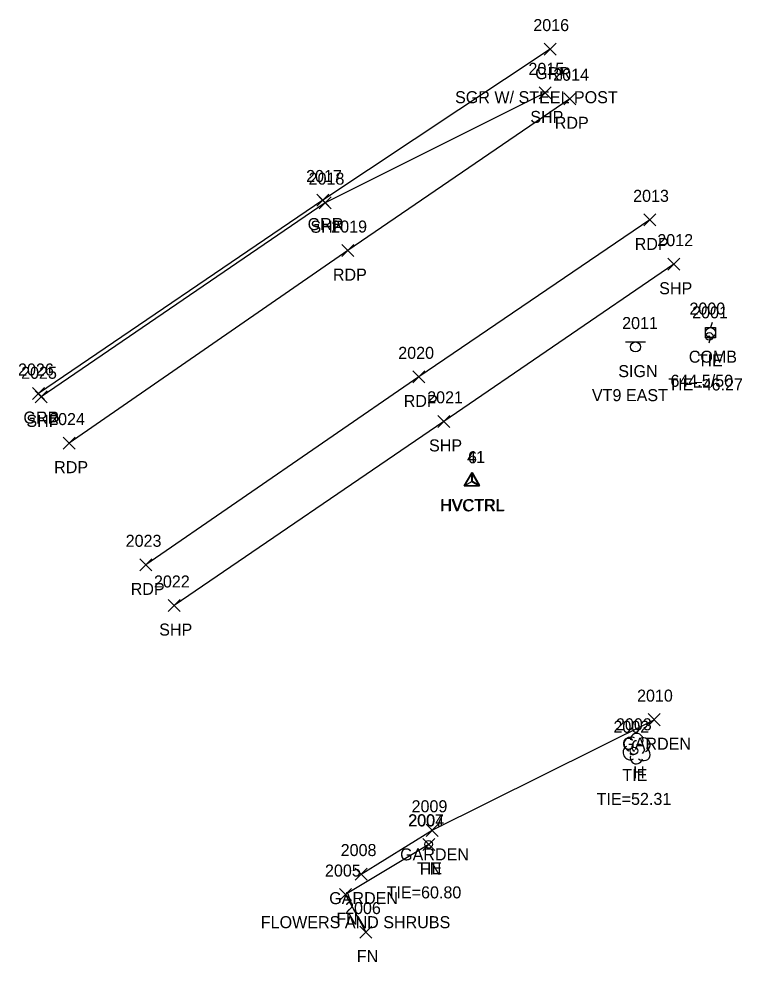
# Model space of a CAD drawing. Extents: x 1502194 to 1507887, y 142265 to 144150.
# Drawn here: x 1507324.3 to 1507444.5, y 143750.3 to 143907.2 of the extents above; entities that cross this region are included whole.
import ezdxf

# ---------------------------------------------------------------- set-up
doc = ezdxf.new("R2010")
doc.units = 0
for name, color, linetype in [('C_A', 7, 'Continuous'), ('C_C', 7, 'Continuous'), ('C_I', 7, 'Continuous'), ('CBP', 7, 'Continuous'), ('CPSM', 7, 'Continuous'), ('L_A', 7, 'Continuous'), ('L_C', 7, 'Continuous'), ('L_I', 7, 'Continuous'), ('L_TIC', 7, 'Continuous'), ('LAPB', 7, 'Continuous'), ('LFNC', 7, 'Continuous'), ('LTD', 7, 'Continuous'), ('P_A', 7, 'Continuous'), ('P_I', 7, 'Continuous'), ('P_TIC', 7, 'Continuous'), ('PET', 7, 'Continuous'), ('PSP', 7, 'Continuous'), ('R_A', 7, 'Continuous'), ('R_C', 7, 'Continuous'), ('R_I', 7, 'Continuous'), ('R_TIC', 7, 'Continuous'), ('RGR', 7, 'Continuous'), ('S_A', 7, 'Continuous'), ('S_C', 7, 'Continuous'), ('S_I', 7, 'Continuous'), ('SSGN', 7, 'Continuous'), ('U_A', 7, 'Continuous'), ('U_C', 7, 'Continuous'), ('U_I', 7, 'Continuous'), ('UP', 7, 'Continuous')]:
    doc.layers.add(name, color=color, linetype=linetype)

msp = doc.modelspace()

# ---------------------------------------------------------------- linework, layer by layer
at = {"layer": 'CBP'}
for centre, radius in [((1507439.08, 143854.37), 0.625), ((1507439.08, 143854.37), 0.0833), ((1507426.55, 143785.42), 0.625), ((1507426.55, 143785.42), 0.0833), ((1507392.41, 143769.87), 0.625), ((1507392.41, 143769.87), 0.0833)]:
    msp.add_circle(centre, radius, dxfattribs=at)
at = {"layer": 'CPSM'}
for p, q in [((1507398.34, 143829.53), (1507399.59, 143831.69)), ((1507398.45, 143829.58), (1507399.7, 143831.74)), ((1507400.84, 143829.53), (1507399.59, 143831.69)), ((1507399.59, 143830.25), (1507399.59, 143831.69)), ((1507400.95, 143829.58), (1507399.7, 143831.74)), ((1507399.7, 143830.3), (1507399.7, 143831.74)), ((1507398.34, 143829.53), (1507399.59, 143830.25)), ((1507398.45, 143829.58), (1507399.7, 143830.3)), ((1507399.59, 143830.25), (1507399.59, 143830.25)), ((1507399.59, 143830.25), (1507400.84, 143829.53)), ((1507399.7, 143830.3), (1507399.7, 143830.3)), ((1507399.7, 143830.3), (1507400.95, 143829.58)), ((1507398.34, 143829.53), (1507400.84, 143829.53)), ((1507398.45, 143829.58), (1507400.95, 143829.58))]:
    msp.add_line(p, q, dxfattribs=at)
at = {"layer": 'L_TIC'}
for points in [[(1507428.93, 143789.6), (1507430.93, 143791.6)], [(1507430.93, 143789.6), (1507428.93, 143791.6)], [(1507392, 143771.19), (1507394, 143773.19)], [(1507394, 143771.19), (1507392, 143773.19)], [(1507391.47, 143768.84), (1507393.47, 143770.84)], [(1507393.47, 143768.84), (1507391.47, 143770.84)], [(1507380.21, 143763.91), (1507382.21, 143765.91)], [(1507382.21, 143763.91), (1507380.21, 143765.91)], [(1507377.59, 143760.5), (1507379.59, 143762.5)], [(1507379.59, 143760.5), (1507377.59, 143762.5)], [(1507380.99, 143754.26), (1507382.99, 143756.26)], [(1507382.99, 143754.26), (1507380.99, 143756.26)]]:
    msp.add_lwpolyline(points, dxfattribs=at)
at = {"layer": 'LAPB'}
msp.add_lwpolyline([(1507381.21, 143764.91), (1507393, 143772.19), (1507429.93, 143790.6)], dxfattribs=at)
at = {"layer": 'LFNC'}
msp.add_lwpolyline([(1507392.47, 143769.84), (1507378.59, 143761.5), (1507381.99, 143755.26)], dxfattribs=at)
at = {"layer": 'LTD'}
msp.add_line((1507426.97, 143785.83), (1507426.97, 143785.83), dxfattribs=at)
msp.add_line((1507426.97, 143785.83), (1507426.97, 143785.83), dxfattribs=at)
msp.add_arc((1507427.02, 143787.26), 1.05, 335.5272, 180.9563, dxfattribs=at)
for centre, major_axis, ratio, start_param, end_param in [((1507426.18, 143786.49), (1.21, -0.51), 0.895232, 1.570796, 4.712389), ((1507428.02, 143786.41), (-1.14, -0.48), 0.949671, 1.570796, 4.712389), ((1507426.77, 143786.28), (-0.208, -0.792), 0.645439, 3.141593, 6.283185), ((1507427.47, 143785.66), (-0.5, 0.667), 0.989748, 3.141593, 6.283185), ((1507425.89, 143785.12), (0.58, -1.04), 0.959034, 3.141593, 6.283185), ((1507426.52, 143785.08), (-0.625, -0.083), 0.423636, 0, 3.141593), ((1507427.97, 143784.99), (-1.09, 0.79), 0.841452, 1.570796, 4.712389), ((1507426.97, 143784.33), (0.26, 1.06), 0.942809, 1.570796, 4.712389)]:
    msp.add_ellipse(centre, major_axis=major_axis, ratio=ratio, start_param=start_param, end_param=end_param, dxfattribs=at)
at = {"layer": 'P_TIC'}
for points in [[(1507410.79, 143893.88), (1507412.79, 143895.88)], [(1507412.79, 143893.88), (1507410.79, 143895.88)], [(1507414.9, 143892.9), (1507416.9, 143894.9)], [(1507416.9, 143892.9), (1507414.9, 143894.9)], [(1507374.23, 143875.61), (1507376.23, 143877.61)], [(1507376.23, 143875.61), (1507374.23, 143877.61)], [(1507428.19, 143872.75), (1507430.19, 143874.75)], [(1507430.19, 143872.75), (1507428.19, 143874.75)], [(1507378, 143867.64), (1507380, 143869.64)], [(1507380, 143867.64), (1507378, 143869.64)], [(1507432.21, 143865.38), (1507434.21, 143867.38)], [(1507434.21, 143865.38), (1507432.21, 143867.38)], [(1507389.78, 143846.63), (1507391.78, 143848.63)], [(1507391.78, 143846.63), (1507389.78, 143848.63)], [(1507326.99, 143843.31), (1507328.99, 143845.31)], [(1507328.99, 143843.31), (1507326.99, 143845.31)], [(1507393.94, 143839.23), (1507395.94, 143841.23)], [(1507395.94, 143839.23), (1507393.94, 143841.23)], [(1507331.65, 143835.61), (1507333.65, 143837.61)], [(1507333.65, 143835.61), (1507331.65, 143837.61)], [(1507344.38, 143815.36), (1507346.38, 143817.36)], [(1507346.38, 143815.36), (1507344.38, 143817.36)], [(1507349.08, 143808.59), (1507351.08, 143810.59)], [(1507351.08, 143808.59), (1507349.08, 143810.59)]]:
    msp.add_lwpolyline(points, dxfattribs=at)
at = {"layer": 'PET'}
for points in [[(1507415.9, 143893.9), (1507379, 143868.64), (1507332.65, 143836.61)], [(1507429.19, 143873.75), (1507390.78, 143847.63), (1507345.38, 143816.36)]]:
    msp.add_lwpolyline(points, dxfattribs=at)
at = {"layer": 'PSP'}
for points in [[(1507411.79, 143894.88), (1507375.23, 143876.61), (1507327.99, 143844.31)], [(1507433.21, 143866.38), (1507394.94, 143840.23), (1507350.08, 143809.59)]]:
    msp.add_lwpolyline(points, dxfattribs=at)
at = {"layer": 'R_TIC'}
for points in [[(1507411.64, 143901.16), (1507413.64, 143903.16)], [(1507413.64, 143901.16), (1507411.64, 143903.16)], [(1507373.81, 143876.05), (1507375.81, 143878.05)], [(1507375.81, 143876.05), (1507373.81, 143878.05)], [(1507326.54, 143843.86), (1507328.54, 143845.86)], [(1507328.54, 143843.86), (1507326.54, 143845.86)]]:
    msp.add_lwpolyline(points, dxfattribs=at)
at = {"layer": 'RGR'}
msp.add_lwpolyline([(1507412.64, 143902.16), (1507374.81, 143877.05), (1507327.54, 143844.86)], dxfattribs=at)
at = {"layer": 'SSGN'}
for p, q in [((1507425.17, 143853.45), (1507428.5, 143853.45)), ((1507426.81, 143852.61), (1507426.81, 143852.61))]:
    msp.add_line(p, q, dxfattribs=at)
msp.add_circle((1507426.81, 143852.61), 0.833, dxfattribs=at)
at = {"layer": 'UP'}
for p, q in [((1507438.45, 143854.15), (1507438.45, 143855.82)), ((1507438.45, 143855.82), (1507440.12, 143855.82)), ((1507439.54, 143856.65), (1507439.29, 143855.82)), ((1507440.12, 143855.82), (1507440.12, 143854.15)), ((1507440.12, 143854.15), (1507438.45, 143854.15)), ((1507439.04, 143853.32), (1507439.29, 143854.15)), ((1507439.29, 143854.99), (1507439.29, 143854.99))]:
    msp.add_line(p, q, dxfattribs=at)
msp.add_circle((1507439.29, 143854.99), 0.833, dxfattribs=at)

# ---------------------------------------------------------------- texts
at = {"layer": 'C_A'}
for s, p in [('TIE', (1507437.16, 143849.37)), ('HVCTRL', (1507394.28, 143825.25)), ('HVCTRL', (1507394.4, 143825.3)), ('TIE', (1507424.63, 143780.42)), ('TIE', (1507390.49, 143764.87))]:
    msp.add_text(s, height=2, dxfattribs=at).set_placement(p)
at = {"layer": 'C_C'}
for s, p in [('TIE=46.27', (1507432.26, 143845.37)), ('TIE=52.31', (1507420.35, 143776.42)), ('TIE=60.80', (1507385.43, 143760.87))]:
    msp.add_text(s, height=2, dxfattribs=at).set_placement(p)
at = {"layer": 'C_I'}
for s, p in [('2001', (1507436.23, 143857.37)), ('41', (1507398.81, 143833.3)), ('6', (1507398.96, 143833.25)), ('2002', (1507423.14, 143788.42)), ('2007', (1507389, 143772.87))]:
    msp.add_text(s, height=2, dxfattribs=at).set_placement(p)
at = {"layer": 'L_A'}
for s, p in [('GARDEN', (1507424.6, 143785.6)), ('H', (1507426.41, 143780.83)), ('GARDEN', (1507387.67, 143767.19)), ('FN', (1507390.95, 143764.84)), ('GARDEN', (1507375.88, 143759.91)), ('FN', (1507377.07, 143756.5)), ('FN', (1507380.47, 143750.26))]:
    msp.add_text(s, height=2, dxfattribs=at).set_placement(p)
at = {"layer": 'L_C'}
msp.add_text('FLOWERS AND SHRUBS', height=2, dxfattribs=at).set_placement((1507364.51, 143755.91))
at = {"layer": 'L_I'}
for s, p in [('2010', (1507427.07, 143793.6)), ('2003', (1507423.56, 143788.83)), ('2009', (1507389.58, 143775.19)), ('2004', (1507389.05, 143772.84)), ('2008', (1507377.79, 143767.91)), ('2005', (1507375.18, 143764.5)), ('2006', (1507378.52, 143758.26))]:
    msp.add_text(s, height=2, dxfattribs=at).set_placement(p)
at = {"layer": 'P_A'}
for s, p in [('SHP', (1507409.32, 143889.88)), ('RDP', (1507413.39, 143888.9)), ('SHP', (1507372.76, 143871.61)), ('RDP', (1507426.68, 143868.75)), ('RDP', (1507376.49, 143863.64)), ('SHP', (1507430.75, 143861.38)), ('RDP', (1507388.27, 143842.63)), ('SHP', (1507325.53, 143839.31)), ('SHP', (1507392.48, 143835.23)), ('RDP', (1507330.14, 143831.61)), ('RDP', (1507342.87, 143811.36)), ('SHP', (1507347.61, 143804.59))]:
    msp.add_text(s, height=2, dxfattribs=at).set_placement(p)
at = {"layer": 'P_I'}
for s, p in [('2015', (1507409.01, 143897.88)), ('2014', (1507413.13, 143896.9)), ('2018', (1507372.46, 143879.61)), ('2013', (1507426.42, 143876.75)), ('2019', (1507376.22, 143871.64)), ('2012', (1507430.44, 143869.38)), ('2020', (1507387.36, 143850.63)), ('2025', (1507324.65, 143847.31)), ('2021', (1507392.17, 143843.23)), ('2024', (1507329.31, 143839.61)), ('2023', (1507342.04, 143819.36)), ('2022', (1507346.74, 143812.59))]:
    msp.add_text(s, height=2, dxfattribs=at).set_placement(p)
at = {"layer": 'R_A'}
for p in [(1507410.13, 143897.16), (1507372.3, 143872.05), (1507325.03, 143839.86)]:
    msp.add_text('GRR', height=2, dxfattribs=at).set_placement(p)
at = {"layer": 'R_C'}
msp.add_text('SGR W/ STEEL POST', height=2, dxfattribs=at).set_placement((1507396.81, 143893.16))
at = {"layer": 'R_I'}
for s, p in [('2016', (1507409.82, 143905.16)), ('2017', (1507372.04, 143880.05)), ('2026', (1507324.14, 143847.86))]:
    msp.add_text(s, height=2, dxfattribs=at).set_placement(p)
at = {"layer": 'S_A'}
msp.add_text('SIGN', height=2, dxfattribs=at).set_placement((1507423.95, 143847.59))
at = {"layer": 'S_C'}
msp.add_text('VT9 EAST', height=2, dxfattribs=at).set_placement((1507419.57, 143843.59))
at = {"layer": 'S_I'}
msp.add_text('2011', height=2, dxfattribs=at).set_placement((1507424.59, 143855.59))
at = {"layer": 'U_A'}
msp.add_text('COMB', height=2, dxfattribs=at).set_placement((1507435.67, 143849.99))
at = {"layer": 'U_C'}
msp.add_text('644.5/50', height=2, dxfattribs=at).set_placement((1507432.63, 143845.99))
at = {"layer": 'U_I'}
msp.add_text('2000', height=2, dxfattribs=at).set_placement((1507435.78, 143857.99))

doc.saveas('drawing.dxf')
